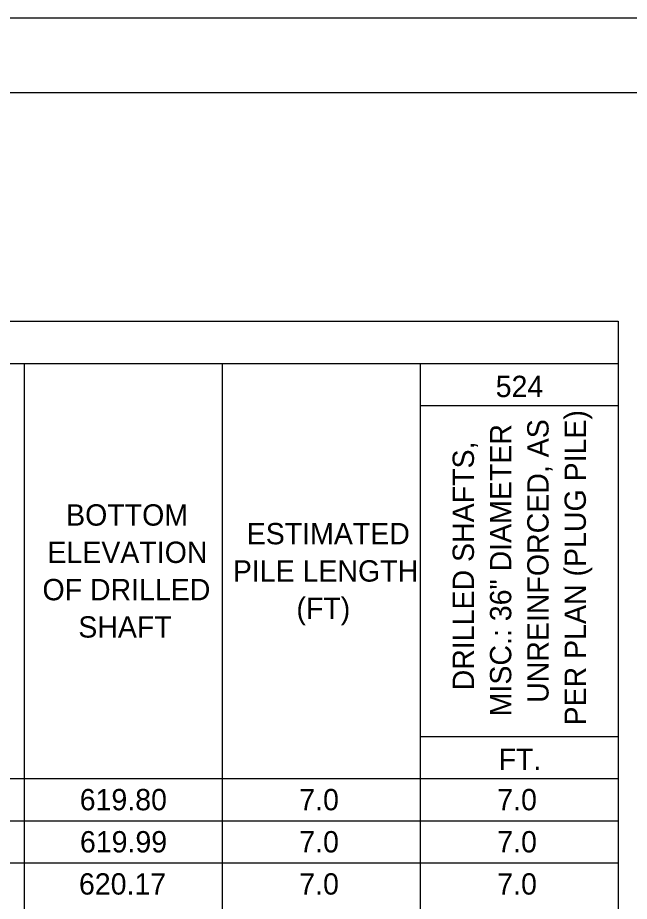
# Model space of a CAD drawing. Extents: x -0.2 to 33.8, y -0.1 to 21.9.
# Drawn here: x 26.36 to 30.45, y 15.95 to 21.87 of the extents above; entities that cross this region are included whole.
import ezdxf

# ---------------------------------------------------------------- set-up
doc = ezdxf.new("R2010")
doc.units = 0
for name, color, linetype in [('BR_P_Gen_Text', 7, 'Continuous'), ('SH_Border', 7, 'Continuous'), ('SH_Cut_Line', 7, 'Continuous')]:
    doc.layers.add(name, color=color, linetype=linetype)

msp = doc.modelspace()

# ---------------------------------------------------------------- linework, layer by layer
at = {"layer": 'BR_P_Gen_Text'}
for p, q in [((17.7383, 19.8361), (30.3786, 19.8361)), ((30.3786, 19.8361), (30.3786, 2.6673)), ((17.7383, 19.554), (30.3786, 19.554)), ((26.4003, 19.554), (26.4003, 2.9494)), ((27.7264, 19.554), (27.7264, 2.9494)), ((29.0525, 19.554), (29.0525, 2.6673)), ((29.0525, 19.2718), (30.3786, 19.2718)), ((29.0525, 17.0569), (30.3786, 17.0569)), ((17.7383, 16.7748), (30.3786, 16.7748)), ((17.7383, 16.4926), (30.3786, 16.4926)), ((17.7383, 16.2105), (30.3786, 16.2105))]:
    msp.add_line(p, q, dxfattribs=at)
at = {"layer": 'SH_Border'}
msp.add_lwpolyline([(1.7753, 21.368), (33.2753, 21.368), (33.2753, 0.368), (1.7753, 0.368)], close=True, dxfattribs=at)
at = {"layer": 'SH_Cut_Line'}
msp.add_lwpolyline([(-0.2247, 21.868), (33.7753, 21.868), (33.7753, -0.132), (-0.2247, -0.132)], close=True, dxfattribs=at)

# ---------------------------------------------------------------- texts
at = {"layer": 'BR_P_Gen_Text'}
for s, height, p in [('524', 0.14277, (29.5577, 19.3282)), ('BOTTOM', 0.14277, (26.6804, 18.4678)), ('ESTIMATED', 0.14277, (27.8902, 18.3428)), ('ELEVATION', 0.14277, (26.5555, 18.2179)), ('PILE LENGTH', 0.142768, (27.7971, 18.093)), ('OF DRILLED', 0.14277, (26.5221, 17.9681)), ('(FT)', 0.14277, (28.223, 17.8432)), ('SHAFT', 0.14277, (26.7618, 17.7182)), ('FT.', 0.14277, (29.5774, 16.8312)), ('619.80', 0.14277, (26.7715, 16.5623)), ('7.0', 0.14277, (28.2422, 16.5623)), ('7.0', 0.14277, (29.5683, 16.5623)), ('619.99', 0.14277, (26.773, 16.2802)), ('7.0', 0.14277, (28.2422, 16.2802)), ('7.0', 0.14277, (29.5683, 16.2802)), ('620.17', 0.14277, (26.7664, 15.998)), ('7.0', 0.14277, (28.2422, 15.998)), ('7.0', 0.14277, (29.5683, 15.998))]:
    msp.add_text(s, height=height, dxfattribs=at).set_placement(p)
for s, p in [('PER PLAN (PLUG PILE)', (30.1617, 17.13)), ('UNREINFORCED, AS', (29.9118, 17.2812)), ('MISC.: 36" DIAMETER', (29.662, 17.1917)), ('DRILLED SHAFTS,', (29.4121, 17.3652))]:
    msp.add_text(s, height=0.142768, rotation=90, dxfattribs=at).set_placement(p)

doc.saveas('drawing.dxf')
